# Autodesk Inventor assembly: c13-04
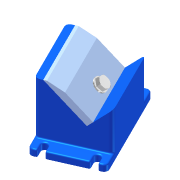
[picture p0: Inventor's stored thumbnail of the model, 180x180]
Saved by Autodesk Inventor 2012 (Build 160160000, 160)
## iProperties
Created: 2010-11
Part Number: c13-04
Document SubType Name: Assembly
Designer: Beta-8540w
Author: Beta-8540w
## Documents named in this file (5)
- C:\Users\VMuser\Desktop\Inventor 2012 Essentials\Assemblies\Chapter 13\c13-04.iam
- C:\Users\VMuser\Desktop\Inventor 2012 Essentials\Content Center Files\en-US\ISO 4017\ISO 4017 - M10 x 35ISO.ipt
- C:\Users\VMuser\Desktop\Inventor 2012 Essentials\Parts\Chapter 13\c13-02.ipt
- C:\Users\VMuser\Desktop\Inventor 2012 Essentials\Content Center Files\en-US\ISO 7091\ISO 7091 - ST 10 - 100 HV.ipt
- C:\Users\VMuser\Desktop\Inventor 2012 Essentials\Parts\Chapter 13\c13-01.ipt
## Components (4 placed, 4 different names)
1. c13-01:1 — Insert:1, Angle:1
2. c13-02:1 — Insert:1, Angle:1, Insert:2
3. ISO 4017 M10 x 35:1 — Insert:3
4. ISO 7091 ST 10 - 100 HV:1 — Insert:2, Insert:3
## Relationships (4: Insert 3, Angle 1)
- Insert:1: c13-01:1 ↔ c13-02:1
- Angle:1: c13-01:1 ↔ c13-02:1
- Insert:2: c13-02:1 ↔ ISO 7091 ST 10 - 100 HV:1
- Insert:3: ISO 4017 M10 x 35:1 ↔ ISO 7091 ST 10 - 100 HV:1
